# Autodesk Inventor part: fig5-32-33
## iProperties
Shininess: 77.0
Angle Display Precision: 2
Document Length Units: 11269
Document Angle Units: 11279
Document Time Units: 11290
Document Mass Units: 11283
Document Length Units Precision: 3
Document Angle Units Precision: 2
Created: 2001-12
Part Number: fig5-32-33
Document SubType Name: Modeling
Designer: Renu Muthoo
Density: 0.0
Volumn: 0.0
Area: 0.0
PropertySet Name: Model Information
Control State: 0
Master: False
Checked Out: False
Author: Renu Muthoo
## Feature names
1. Extrusion1
2. Extrusion3
3. Chamfer3
